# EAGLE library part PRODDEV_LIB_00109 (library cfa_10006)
CFAG12864M-TMI-TN, 128x64 STN Blue, Negative, Transmissive, White LED Edge Backlit LCD Module
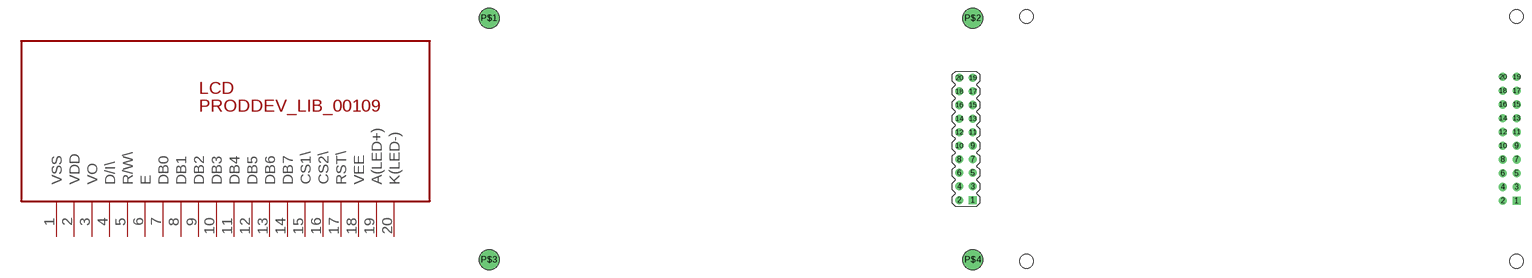
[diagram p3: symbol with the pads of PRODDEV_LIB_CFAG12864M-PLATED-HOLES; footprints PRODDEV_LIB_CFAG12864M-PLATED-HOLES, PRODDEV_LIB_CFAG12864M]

Designator prefix LCD

## PRODDEV_LIB_00109  [PRODDEV_LIB_CFAG12864M-PLATED-HOLES]
1  VSS  pwr
2  VDD  pwr
3  VO  pas
4  D/I\  in
5  R/W\  in
6  E  in
7  DB0
8  DB1
9  DB2
10  DB3
11  DB4
12  DB5
13  DB6
14  DB7
15  CS1\  in
16  CS2\  in
17  RST\  in
18  VEE  pas
19  A(LED+)  pas
20  K(LED-)  pas

## PRODDEV_LIB_00109NON-PLATED-HOLES  [PRODDEV_LIB_CFAG12864M]
Pads as for PRODDEV_LIB_CFAG12864M-PLATED-HOLES

## Footprint PRODDEV_LIB_CFAG12864M-PLATED-HOLES (pad centres in mm)
drill 1 square: 1 0,0
drill 1 round: 2 -2.54,0; 3 0,2.54; 4 -2.54,2.54; 5 0,5.08; 6 -2.54,5.08; 7 0,7.62; 8 -2.54,7.62; 9 0,10.16; 10 -2.54,10.16; 11 0,12.7; 12 -2.54,12.7; 13 0,15.24; 14 -2.54,15.24; 15 0,17.78; 16 -2.54,17.78; 17 0,20.32; 18 -2.54,20.32; 19 0,22.86; 20 -2.54,22.86
drill 2.5 round: P$1 -90.5,34.03; P$2 0,34.03; P$3 -90.5,-11.17; P$4 0,-11.17

## Footprint PRODDEV_LIB_CFAG12864M (pad centres in mm)
drill 1 square: 1 0,0.013
drill 1 round: 2 -2.54,0.013; 3 0,2.553; 4 -2.54,2.553; 5 0,5.093; 6 -2.54,5.093; 7 0,7.633; 8 -2.54,7.633; 9 0,10.173; 10 -2.54,10.173; 11 0,12.713; 12 -2.54,12.713; 13 0,15.253; 14 -2.54,15.253; 15 0,17.793; 16 -2.54,17.793; 17 0,20.333; 18 -2.54,20.333; 19 0,22.873; 20 -2.54,22.873
hole 2.5 at -90.5,-11.157
hole 2.5 at 0,-11.157
hole 2.5 at 0,34.043
hole 2.5 at -90.5,34.043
